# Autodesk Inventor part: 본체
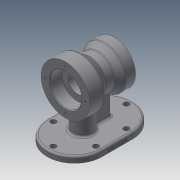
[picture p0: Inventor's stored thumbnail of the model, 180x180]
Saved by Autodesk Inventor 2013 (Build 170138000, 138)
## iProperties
Created: 2020-01
Part Number: 본체
Material: Generic
Document SubType Name: Modeling
Designer: user
Density: 1 g/cm^3
Author: user
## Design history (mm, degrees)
sketch "스케치1"
  geometry: L1 (0, 58)-(0, -22); L2 (0, 58)-(40, 58); L3 (40, 58)-(40, 34); L4 (40, 34)-(27.5, 19.103); L5 (27.5, 19.103)-(27.5, 4.711); L6 (27.5, 4.711)-(35, -6); L7 (35, -6)-(35, -22); L8 (35, -22)-(0, -22); 1 further point
  constraints: 16 end point, 3 parallel, 2 perpendicular, 1 point on line, 1 vertical
  dimensions: "d0" = 80 distance of L1.start L1.end; "d1" = 58 distance of point (0, 0) L1.start; "d2" = 24 distance of L2.end L3.end; "d3" = 16 distance of L6.end L7.end; "d4" = 40 deg angle of L5 L4; "d5" = 35 deg angle of L5 L6; "d6" = 80 diameter of L3 L1; "d7" = 55 diameter of L5 L1; "d8" = 70 diameter of L7 L1
revolve "회전1" sketch "스케치1" stored, may be unused: angle "d9" = 90 deg
sketch "스케치2"
  geometry: C1 r 40 at (0, 0) reference; C2 r 26 at (0, 0)
  constraints: 1 centre point, 1 coincident
  dimensions: "d10" = 52 diameter of C2
extrude "돌출1" cut sketch "스케치2" distance "d11" = 20; taper "d12" = 0 deg
sketch "스케치3"
  geometry: C1 r 35 at (0, 0) reference; C2 r 20 at (0, 0)
  constraints: 1 centre point, 1 coincident
  dimensions: "d13" = 40 diameter of C2
extrude "돌출2" cut sketch "스케치3" distance "d14" = 17; taper "d15" = 0 deg
sketch "스케치4"
  geometry: C1 r 26 at (0, 0) reference; C2 r 16 at (0, 0)
  constraints: 1 centre point, 1 coincident
  dimensions: "d16" = 32 diameter of C2
extrude "돌출3" cut sketch "스케치4" stored distance "d17" = 17; taper "d18" = 0 deg
fillet "모깎기1" dims "d19" = 3, "d20" = 0.3
sketch "스케치5"
  geometry: L1 (0, 0)-(0, 33); C1 r 40 at (0, 0) reference; 1 further point
  constraints: 2 end point, 1 coincident, 1 vertical
  dimensions: "d21" = 33 distance of L1.start L1.end
hole "구멍1" sketch "스케치5" at (0, 33) diameter "d22" = 3.242; stored, may be unused: countersink angle "d26" = 90 deg, drill point angle "d28" = 118 deg; dims "d23" = 9, "d24" = 4, "d25" = 2, "d27" = 11
sketch "스케치6"
  geometry: L1 (0, 0)-(0, 27.5); C1 r 35 at (0, 0) reference; 1 further point
  constraints: 2 end point, 1 coincident, 1 vertical
  dimensions: "d32" = 27.5 distance of L1.start L1.end
hole "구멍2" sketch "스케치6" at (0, 27.5) diameter "d33" = 3.242; stored, may be unused: countersink angle "d37" = 90 deg, drill point angle "d39" = 118 deg; dims "d34" = 9, "d35" = 4, "d36" = 2, "d38" = 11
node "작업 평면1"
sketch "스케치7"
  geometry: L1 (-40, 58)-(40, 58) reference; L2 (45, 43)-(-45, 43); L3 (-45, 43)-(-45, -7); L4 (-45, -7)-(45, -7); L5 (45, -7)-(45, 43); L6 (0, 88)-(0, 43); A1 r 45 centre (0, 43) between (45, 43) and (-45, 43); A2 r 45 centre (0, -7) between (-45, -7) and (45, -7); 2 further points
  constraints: 10 end point, 5 point on circle, 3 parallel, 2 centre point, 2 midpoint, 1 coincident, 1 horizontal, 1 perpendicular, 1 vertical alignment
  dimensions: "d45" = 90 distance of L4.end L3.end; "d46" = 50 distance of L2.end L3.end; "d47" = 30 distance from line of L6.start L1
extrude "돌출4" join sketch "스케치7" distance "d48" = 10; taper "d49" = 0 deg
sketch "스케치8"
  geometry: L1 (45, -43)-(45, 7) reference; L2 (-45, 7)-(-45, -43) reference; L3 (35, 7)-(35, -43); L4 (-35, -43)-(-35, 7); A1 r 45 centre (0, -43) between (-45, -43) and (45, -43) reference; A2 r 45 centre (0, 7) between (45, 7) and (-45, 7) reference; A3 r 35 centre (0, 7) between (35, 7) and (-35, 7); A4 r 35 centre (0, -43) between (-35, -43) and (35, -43); 7 further points
  constraints: 6 point on circle, 4 coincident, 4 end point, 2 centre point, 3 other
  dimensions: "d50" = 10 distance between parallel lines of L4 L2
hole "구멍3" sketch "스케치8" at (-35, -43), (-35, 7), (0, -78), (35, -43), (35, 7), (0, 42) diameter "d51" = 9; stored, may be unused: countersink angle "d55" = 90 deg, drill point angle "d57" = 118 deg; dims "d52" = 9, "d53" = 4, "d54" = 2, "d56" = 11
sketch "스케치9" dims "d33" = 3.242
  geometry: L1 (-45, 7)-(-45, -43) reference; L2 (0, -88)-(0, -30); C1 r 16 at (0, -30); A1 r 45 centre (0, -43) between (-45, -43) and (45, -43) reference; 1 further point
  constraints: 2 end point, 1 centre point, 1 coincident, 1 parallel, 1 point on circle
  dimensions: "d58" = 58 distance of L2.start L2.end; "d59" = 32 diameter of C1
extrude "돌출5" join sketch "스케치9" stored distance "d60" = 10; taper "d61" = 0 deg
sketch "스케치10"
  geometry: L1 (35, -6.946)-(35, -22) reference; L2 (35, -22)-(29.121, -22) reference; L3 (29.121, -22)-(29.121, -11) reference; L4 (29.121, -11)-(27.5, -10.026) reference; L5 (27.5, -10.026)-(25.879, -11) reference; L6 (25.879, -11)-(25.879, -22) reference; L7 (25.879, -22)-(20, -22) reference; L8 (20, -22)-(20, -5.3) reference; L9 (19.7, -5)-(16, -5) reference; L10 (16, -5)-(16, 38) reference; L11 (16, 38)-(25.7, 38) reference; L12 (26, 38.3)-(26, 58) reference; L13 (26, 58)-(31.379, 58) reference; L14 (31.379, 58)-(31.379, 47) reference; L15 (31.379, 47)-(33, 46.026) reference; L16 (33, 46.026)-(34.621, 47) reference; L17 (34.621, 47)-(34.621, 58) reference; L18 (34.621, 58)-(40, 58) reference; L19 (40, 58)-(40, 35.092) reference; L20 (39.298, 33.164)-(28.202, 19.94) reference; L21 (27.5, 18.011)-(27.5, 5.657) reference; L22 (28.043, 3.936)-(34.457, -5.225) reference; L23 (-70, -37.5)-(-80, -37.5) reference; L24 (-80, -37.5)-(-80, 73.5) reference; L25 (-80, 73.5)-(-70, 73.5) reference; L26 (-70, 73.5)-(-70, 46) reference; L27 (-70, 46)-(-40, 46) reference; L28 (-40, 46)-(-40, 58) reference; L29 (-40, 58)-(-34.621, 58) reference; L30 (-34.621, 58)-(-34.621, 47) reference; L31 (-34.621, 47)-(-33, 46.026) reference; L32 (-33, 46.026)-(-31.379, 47) reference; L33 (-31.379, 47)-(-31.379, 58) reference; L34 (-31.379, 58)-(-26, 58) reference; L35 (-26, 58)-(-26, 38.3) reference; L36 (-25.7, 38)-(-16, 38) reference; L37 (-16, 38)-(-16, -5) reference; L38 (-16, -5)-(-19.7, -5) reference; L39 (-20, -5.3)-(-20, -22) reference; L40 (-20, -22)-(-25.879, -22) reference; L41 (-25.879, -22)-(-25.879, -11) reference; L42 (-25.879, -11)-(-27.5, -10.026) reference; L43 (-27.5, -10.026)-(-29.121, -11) reference; L44 (-29.121, -11)-(-29.121, -22) reference; L45 (-29.121, -22)-(-35, -22) reference; L46 (-35, -22)-(-35, -6.946) reference; L47 (-34.457, -5.225)-(-28.043, 3.936) reference; L48 (-27.5, 5.657)-(-27.5, 14) reference; L49 (-27.5, 14)-(-70, 14) reference; L50 (-70, 14)-(-70, -37.5) reference; L51 (-70, -52)-(-80, -52) reference; L52 (-80, -52)-(-80, -46.5) reference; L53 (-80, -46.5)-(-70, -46.5) reference; L54 (-70, -46.5)-(-70, -52) reference; L55 (-80, 88)-(-70, 88) reference; L56 (-70, 88)-(-70, 82.5) reference; L57 (-70, 82.5)-(-80, 82.5) reference; L58 (-80, 82.5)-(-80, 88) reference; L59 (-35, -12)-(-70, -12); A1 r 3 centre (32, -6.946) between (35, -6.946) and (34.457, -5.225) reference; A2 r 0.3 centre (19.7, -5.3) between (20, -5.3) and (19.7, -5) reference; A3 r 0.3 centre (25.7, 38.3) between (25.7, 38) and (26, 38.3) reference; A4 r 3 centre (37, 35.092) between (39.298, 33.164) and (40, 35.092) reference; A5 r 3 centre (30.5, 18.011) between (28.202, 19.94) and (27.5, 18.011) reference; A6 r 3 centre (30.5, 5.657) between (27.5, 5.657) and (28.043, 3.936) reference; A7 r 0.3 centre (-25.7, 38.3) between (-26, 38.3) and (-25.7, 38) reference; A8 r 0.3 centre (-19.7, -5.3) between (-19.7, -5) and (-20, -5.3) reference; A9 r 3 centre (-32, -6.946) between (-34.457, -5.225) and (-35, -6.946) reference; A10 r 3 centre (-30.5, 5.657) between (-28.043, 3.936) and (-27.5, 5.657) reference; 1 further point
  constraints: 2 end point, 2 point on line, 1 perpendicular
  dimensions: "d62" = 10 distance between parallel lines of L59 L45
feature "리브1" sketch "스케치10" dims "d63" = 1, "d64" = 10, "d65" = 0, "d66" = 0, "d67" = 1, "d68" = 1
fillet "모깎기2" dims "d69" = 3
fillet "모깎기3" dims "d70" = 3
chamfer "모따기1" distance "d71" = 1; stored, may be unused: second distance "d72" = 2, angle "d73" = 45 deg
sketch "스케치11"
  geometry: L1 (95, 0)-(50, 0) reference; L2 (0, 7)-(50, 7) reference; L3 (50, 0)-(50, 7) reference; L4 (50, 0)-(0, 0) reference; L5 (0, 0)-(0, 7) reference; L6 (-45, 0)-(-45, 7) reference; 2 further points
  constraints: 1 other
  dimensions: "d74" = 4 distance from line of L1 point (25, 4); "d75" = 70 horizontal distance of point (25, 4) L6.start
feature "엠보싱1" sketch "스케치11" dims "d0" = 80, "d1" = 58, "d2" = 24, "d3" = 16, "d4" = 40 deg, "d5" = 35 deg, "d6" = 80, "d7" = 55, "d8" = 70, "d76" = 0.5, "d77" = 0
node "솔리드1"
pattern_circular "원형 패턴1" dims angle "d30" = 360 deg
pattern_circular "원형 패턴2" dims angle "d41" = 360 deg
node "절단 모서리 투영1"
node "절단 모서리 투영2"
